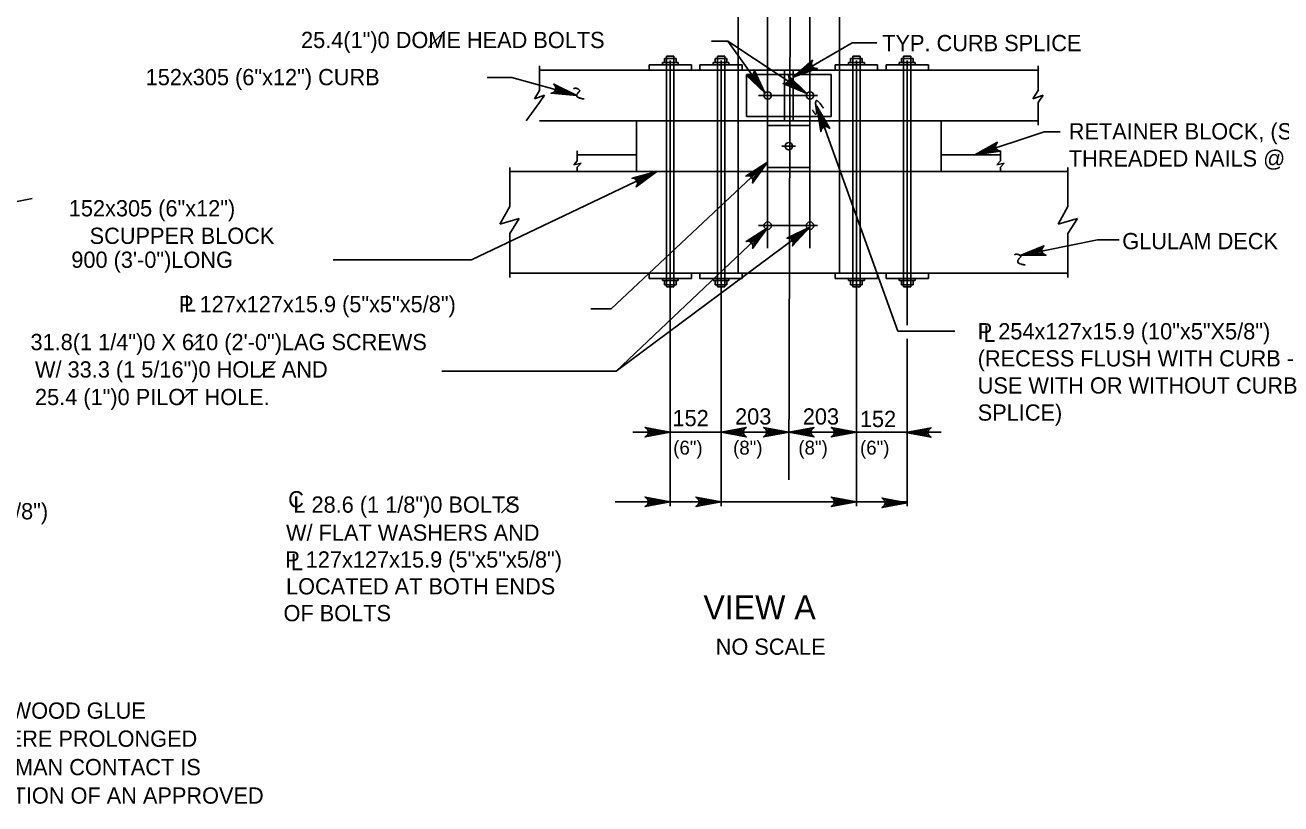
# Model space of a CAD drawing. Extents: x 0 to 36.3, y -66 to 0.
# Drawn here: x 11.08 to 20.36, y -9.1 to -3.35 of the extents above; entities that cross this region are included whole.
import ezdxf

# ---------------------------------------------------------------- set-up
doc = ezdxf.new("R2010")
doc.units = 0
doc.layers.add('2', color=7, linetype='Continuous')
doc.layers.add('3', color=7, linetype='Continuous')

msp = doc.modelspace()

# ---------------------------------------------------------------- linework, layer by layer
at = {"layer": '2'}
for p, q in [((16.3484, -3.2731), (16.3484, -3.6793)), ((17.0984, -3.2731), (17.0984, -3.6793)), ((15.8052, -3.5934), (15.8912, -3.5934)), ((15.8052, -3.5934), (15.8052, -3.6247)), ((15.8209, -3.5778), (15.8756, -3.5778)), ((15.8209, -3.5778), (15.8209, -5.2809)), ((15.8756, -3.5778), (15.8756, -5.2809)), ((15.8912, -3.5934), (15.8912, -3.6247)), ((16.1803, -3.5934), (16.1803, -3.6247)), ((16.1803, -3.5934), (16.2662, -3.5934)), ((16.1959, -3.5778), (16.2506, -3.5778)), ((16.1959, -3.5778), (16.1959, -5.2809)), ((16.2506, -3.5778), (16.2506, -5.2809)), ((16.2662, -3.5934), (16.2662, -3.6247)), ((17.1803, -3.5934), (17.1803, -3.6247)), ((17.1803, -3.5934), (17.2662, -3.5934)), ((17.1959, -3.5778), (17.2506, -3.5778)), ((17.1959, -3.5778), (17.1959, -5.2809)), ((17.2506, -3.5778), (17.2506, -5.2809)), ((17.2662, -3.5934), (17.2662, -3.6247)), ((17.5553, -3.5934), (17.5553, -3.6247)), ((17.5553, -3.5934), (17.6412, -3.5934)), ((17.5709, -3.5778), (17.6256, -3.5778)), ((17.5709, -3.5778), (17.5709, -5.2809)), ((17.6256, -3.5778), (17.6256, -5.2809)), ((17.6412, -3.5934), (17.6412, -3.6247)), ((14.8827, -3.6481), (14.8827, -3.8301)), ((14.8827, -3.6793), (18.5641, -3.6793)), ((15.692, -3.6403), (15.692, -3.6793)), ((16.0045, -3.6403), (15.692, -3.6403)), ((15.7897, -3.6247), (15.9068, -3.6247)), ((15.7897, -3.6247), (15.7897, -3.6403)), ((15.9068, -3.6247), (15.9068, -3.6403)), ((16.0045, -3.6403), (16.0045, -3.6793)), ((16.067, -3.6403), (16.067, -3.6793)), ((16.3795, -3.6403), (16.067, -3.6403)), ((16.1647, -3.6247), (16.2818, -3.6247)), ((16.1647, -3.6247), (16.1647, -3.6403)), ((16.2818, -3.6247), (16.2818, -3.6403)), ((16.3484, -3.6793), (16.3484, -5.1793)), ((16.3795, -3.6403), (16.3795, -3.6793)), ((16.6922, -3.6793), (16.6922, -4.0543)), ((16.7547, -3.6793), (16.7547, -4.0543)), ((17.067, -3.6403), (17.067, -3.6793)), ((17.3795, -3.6403), (17.067, -3.6403)), ((17.0984, -3.6793), (17.0984, -5.1793)), ((17.1647, -3.6247), (17.2818, -3.6247)), ((17.1647, -3.6247), (17.1647, -3.6403)), ((17.2818, -3.6247), (17.2818, -3.6403)), ((17.3795, -3.6403), (17.3795, -3.6793)), ((17.7545, -3.6403), (17.442, -3.6403)), ((17.442, -3.6403), (17.442, -3.6793)), ((17.5397, -3.6247), (17.6568, -3.6247)), ((17.5397, -3.6247), (17.5397, -3.6403)), ((17.6568, -3.6247), (17.6568, -3.6403)), ((17.7545, -3.6403), (17.7545, -3.6793)), ((18.5641, -3.6481), (18.5641, -3.8301)), ((16.4109, -3.713), (17.0359, -3.713)), ((16.4109, -3.713), (16.4109, -4.0231)), ((17.0359, -3.713), (17.0359, -4.0231)), ((14.8827, -3.8301), (14.8454, -3.892)), ((14.8454, -3.892), (14.9197, -3.8642)), ((14.9197, -3.8642), (14.8827, -3.9198)), ((18.5641, -3.8301), (18.5268, -3.892)), ((18.5268, -3.892), (18.6011, -3.8642)), ((18.6011, -3.8642), (18.5641, -3.9198)), ((14.8827, -3.9198), (14.7831, -4.0545)), ((18.5641, -3.9198), (18.5641, -4.0856)), ((14.8827, -4.0543), (18.5641, -4.0543)), ((15.5984, -4.0543), (15.5984, -4.4293)), ((16.4109, -4.0231), (17.0359, -4.0231)), ((17.8484, -4.0543), (17.8484, -4.4293)), ((16.5672, -4.088), (16.5672, -4.3981)), ((16.5672, -4.088), (16.8797, -4.088)), ((16.8797, -4.088), (16.8797, -4.3981)), ((16.673, -4.2418), (16.7722, -4.2418)), ((15.1609, -4.3502), (15.1351, -4.3781)), ((15.1609, -4.2763), (15.1609, -4.3502)), ((15.1609, -4.3043), (15.5984, -4.3043)), ((17.8484, -4.3043), (18.2859, -4.3043)), ((18.2859, -4.3502), (18.2601, -4.3781)), ((18.2859, -4.2763), (18.2859, -4.3502)), ((14.6625, -4.3981), (14.6625, -4.6877)), ((14.6625, -4.4293), (18.7843, -4.4293)), ((15.1351, -4.3781), (15.1898, -4.3667)), ((15.1898, -4.3667), (15.1609, -4.3966)), ((15.1609, -4.3966), (15.1609, -4.4293)), ((16.5672, -4.3981), (16.8797, -4.3981)), ((18.2601, -4.3781), (18.3147, -4.3667)), ((18.3147, -4.3667), (18.2859, -4.3966)), ((18.2859, -4.3966), (18.2859, -4.4293)), ((18.7843, -4.3981), (18.7843, -4.6877)), ((14.6625, -4.6877), (14.5902, -4.8166)), ((18.7843, -4.6877), (18.7119, -4.8166)), ((14.5902, -4.8166), (14.7327, -4.7757)), ((14.7327, -4.7757), (14.6625, -4.8864)), ((18.7119, -4.8166), (18.8545, -4.7757)), ((18.8545, -4.7757), (18.7843, -4.8864)), ((14.6625, -4.8864), (14.6625, -5.2106)), ((18.7843, -4.8864), (18.7843, -5.2106)), ((14.6625, -5.1793), (18.7843, -5.1793)), ((15.692, -5.2184), (15.692, -5.1793)), ((16.0045, -5.2184), (16.0045, -5.1793)), ((16.067, -5.2184), (16.067, -5.1793)), ((16.3795, -5.2184), (16.3795, -5.1793)), ((17.067, -5.2184), (17.067, -5.1793)), ((17.3795, -5.2184), (17.3795, -5.1793)), ((17.442, -5.2184), (17.442, -5.1793)), ((17.7545, -5.2184), (17.7545, -5.1793)), ((16.0045, -5.2184), (15.692, -5.2184)), ((15.7897, -5.2341), (15.7897, -5.2184)), ((15.7897, -5.2341), (15.9068, -5.2341)), ((15.8052, -5.2653), (15.8052, -5.2341)), ((15.8052, -5.2653), (15.8912, -5.2653)), ((15.8209, -5.2809), (15.8756, -5.2809)), ((15.8912, -5.2653), (15.8912, -5.2341)), ((15.9068, -5.2341), (15.9068, -5.2184)), ((16.3795, -5.2184), (16.067, -5.2184)), ((16.1647, -5.2341), (16.1647, -5.2184)), ((16.1647, -5.2341), (16.2818, -5.2341)), ((16.1803, -5.2653), (16.1803, -5.2341)), ((16.1803, -5.2653), (16.2662, -5.2653)), ((16.1959, -5.2809), (16.2506, -5.2809)), ((16.2662, -5.2653), (16.2662, -5.2341)), ((16.2818, -5.2341), (16.2818, -5.2184)), ((17.3795, -5.2184), (17.067, -5.2184)), ((17.1647, -5.2341), (17.1647, -5.2184)), ((17.1647, -5.2341), (17.2818, -5.2341)), ((17.1803, -5.2653), (17.1803, -5.2341)), ((17.1803, -5.2653), (17.2662, -5.2653)), ((17.1959, -5.2809), (17.2506, -5.2809)), ((17.2662, -5.2653), (17.2662, -5.2341)), ((17.2818, -5.2341), (17.2818, -5.2184)), ((17.7545, -5.2184), (17.442, -5.2184)), ((17.5397, -5.2341), (17.5397, -5.2184)), ((17.5397, -5.2341), (17.6568, -5.2341)), ((17.5553, -5.2653), (17.5553, -5.2341)), ((17.5553, -5.2653), (17.6412, -5.2653)), ((17.5709, -5.2809), (17.6256, -5.2809)), ((17.6412, -5.2653), (17.6412, -5.2341)), ((17.6568, -5.2341), (17.6568, -5.2184))]:
    msp.add_line(p, q, dxfattribs=at)
for centre in [(16.5672, -3.8669), (16.8797, -3.8669), (16.7234, -4.2419), (16.5672, -4.8286), (16.8797, -4.8286)]:
    msp.add_circle(centre, 0.0273, dxfattribs=at)
at = {"layer": '3'}
for p, q in [((16.7368, -1.4887), (16.7234, -6.7043)), ((16.5672, -2.1467), (16.5672, -4.994)), ((16.8797, -2.1467), (16.8797, -4.994)), ((14.0634, -3.5122), (14.1826, -3.393)), ((16.2725, -3.467), (16.1525, -3.467)), ((16.5472, -3.8483), (16.2725, -3.467)), ((16.8565, -3.8523), (16.2725, -3.467)), ((16.7547, -3.7311), (17.1906, -3.4787)), ((17.1906, -3.4787), (17.3745, -3.4787)), ((15.8484, -3.6095), (15.8484, -6.8987)), ((16.2234, -3.6095), (16.2234, -6.8987)), ((17.2234, -3.6095), (17.2234, -6.8987)), ((17.5984, -3.6095), (17.5984, -5.5642)), ((14.6769, -3.7332), (14.4954, -3.7332)), ((15.1572, -3.8669), (14.6769, -3.7332)), ((16.4994, -3.8668), (16.9362, -3.8668)), ((16.9306, -3.9465), (17.5277, -5.6086)), ((18.0983, -4.3043), (18.6085, -4.1353)), ((18.6085, -4.1353), (18.7285, -4.1353)), ((15.7489, -4.4293), (14.381, -5.0798)), ((16.5672, -4.3607), (15.411, -5.4423)), ((10.5034, -4.7528), (11.1361, -4.6288)), ((16.8797, -4.8385), (15.4482, -5.9023)), ((16.5672, -4.8436), (15.4482, -5.9023)), ((16.4994, -4.8285), (16.9362, -4.8285)), ((18.4324, -5.0499), (19.0042, -4.9333)), ((19.0042, -4.9333), (19.1629, -4.9333)), ((14.381, -5.0799), (13.3579, -5.0799)), ((15.411, -5.4423), (15.2622, -5.4423)), ((12.2935, -5.7468), (12.4016, -5.6387)), ((17.5277, -5.6086), (17.9496, -5.6086)), ((17.5984, -5.6651), (17.5984, -6.8987)), ((12.8198, -5.9429), (12.9324, -5.8303)), ((15.4482, -5.9023), (14.161, -5.9023)), ((12.2218, -6.1395), (12.3231, -6.0383)), ((15.5712, -6.3537), (17.8485, -6.3537)), ((14.6014, -6.9501), (14.7197, -6.8318)), ((15.4414, -6.8675), (17.5984, -6.8675))]:
    msp.add_line(p, q, dxfattribs=at)
for points in [[(16.7547, -3.7311), (16.8985, -3.6074), (16.8911, -3.6233), (16.8909, -3.6378), (16.8953, -3.6497), (16.9034, -3.6594), (16.9161, -3.6665), (16.9335, -3.6679), (16.7547, -3.7311), (16.9161, -3.6665), (16.9034, -3.6594), (16.7547, -3.7311), (16.8953, -3.6497), (16.8909, -3.6378), (16.7547, -3.7311), (16.8911, -3.6233)], [(16.5472, -3.8483), (16.4098, -3.7175), (16.4263, -3.7233), (16.4408, -3.7221), (16.4522, -3.7165), (16.4611, -3.7074), (16.4669, -3.6941), (16.4666, -3.6767), (16.5472, -3.8483), (16.4669, -3.6941), (16.4611, -3.7074), (16.5472, -3.8483), (16.4522, -3.7165), (16.4408, -3.7221), (16.5472, -3.8483), (16.4263, -3.7233)], [(15.1572, -3.8669), (14.9683, -3.8506), (14.9848, -3.8448), (14.9952, -3.8348), (15.0007, -3.8233), (15.002, -3.8108), (14.9982, -3.7967), (14.9871, -3.7832), (15.1572, -3.8669), (14.9982, -3.7967), (15.002, -3.8108), (15.1572, -3.8669), (15.0007, -3.8233), (14.9952, -3.8348), (15.1572, -3.8669), (14.9848, -3.8448)], [(16.8565, -3.8523), (16.6817, -3.7788), (16.6991, -3.7784), (16.7122, -3.7721), (16.7208, -3.7628), (16.726, -3.7512), (16.7267, -3.7367), (16.7202, -3.7205), (16.8565, -3.8523), (16.7267, -3.7367), (16.726, -3.7512), (16.8565, -3.8523), (16.7208, -3.7628), (16.7122, -3.7721), (16.8565, -3.8523), (16.6991, -3.7784)], [(16.9306, -3.9465), (17.0265, -4.1101), (17.0122, -4.1), (16.998, -4.0972), (16.9855, -4.0994), (16.9745, -4.1057), (16.9653, -4.1168), (16.9608, -4.1338), (16.9306, -3.9465), (16.9653, -4.1168), (16.9745, -4.1057), (16.9306, -3.9465), (16.9855, -4.0994), (16.998, -4.0972), (16.9306, -3.9465), (17.0122, -4.1)], [(18.0983, -4.3043), (18.2643, -4.2125), (18.2538, -4.2265), (18.2507, -4.2407), (18.2526, -4.2532), (18.2586, -4.2644), (18.2695, -4.2739), (18.2862, -4.2788), (18.0983, -4.3043), (18.2695, -4.2739), (18.2586, -4.2644), (18.0983, -4.3043), (18.2526, -4.2532), (18.2507, -4.2407), (18.0983, -4.3043), (18.2538, -4.2265)], [(15.7489, -4.4293), (15.5956, -4.5409), (15.6042, -4.5258), (15.6056, -4.5113), (15.6022, -4.4991), (15.5948, -4.4887), (15.5828, -4.4807), (15.5656, -4.4778), (15.7489, -4.4293), (15.5828, -4.4807), (15.5948, -4.4887), (15.7489, -4.4293), (15.6022, -4.4991), (15.6056, -4.5113), (15.7489, -4.4293), (15.6042, -4.5258)], [(16.5672, -4.3607), (16.4549, -4.5137), (16.4586, -4.4966), (16.4555, -4.4823), (16.4485, -4.4718), (16.4384, -4.4641), (16.4244, -4.46), (16.4072, -4.4626), (16.5672, -4.3607), (16.4244, -4.46), (16.4384, -4.4641), (16.5672, -4.3607), (16.4485, -4.4718), (16.4555, -4.4823), (16.5672, -4.3607), (16.4586, -4.4966)], [(16.5672, -4.8436), (16.4557, -4.9971), (16.4594, -4.98), (16.4562, -4.9658), (16.4492, -4.9552), (16.439, -4.9477), (16.425, -4.9437), (16.4078, -4.9463), (16.5672, -4.8436), (16.425, -4.9437), (16.439, -4.9477), (16.5672, -4.8436), (16.4492, -4.9552), (16.4562, -4.9658), (16.5672, -4.8436), (16.4594, -4.98)], [(16.8797, -4.8385), (16.7509, -4.9777), (16.7565, -4.9612), (16.755, -4.9467), (16.7492, -4.9354), (16.7401, -4.9267), (16.7267, -4.9211), (16.7092, -4.9217), (16.8797, -4.8385), (16.7267, -4.9211), (16.7401, -4.9267), (16.8797, -4.8385), (16.7492, -4.9354), (16.755, -4.9467), (16.8797, -4.8385), (16.7565, -4.9612)], [(18.4324, -5.0499), (18.6081, -4.9784), (18.596, -4.991), (18.5912, -5.0047), (18.5917, -5.0174), (18.5962, -5.0293), (18.606, -5.04), (18.6221, -5.0469), (18.4324, -5.0499), (18.606, -5.04), (18.5962, -5.0293), (18.4324, -5.0499), (18.5917, -5.0174), (18.5912, -5.0047), (18.4324, -5.0499), (18.596, -4.991)], [(15.8484, -6.3537), (15.662, -6.3886), (15.6763, -6.3787), (15.6837, -6.3662), (15.6859, -6.3537), (15.6837, -6.3412), (15.6763, -6.3287), (15.662, -6.3187), (15.8484, -6.3537), (15.6763, -6.3287), (15.6837, -6.3412), (15.8484, -6.3537), (15.6859, -6.3537), (15.6837, -6.3662), (15.8484, -6.3537), (15.6763, -6.3787)], [(16.2234, -6.3537), (16.4098, -6.3187), (16.3955, -6.3287), (16.3881, -6.3412), (16.3859, -6.3537), (16.3881, -6.3662), (16.3955, -6.3787), (16.4098, -6.3886), (16.2234, -6.3537), (16.3955, -6.3787), (16.3881, -6.3662), (16.2234, -6.3537), (16.3859, -6.3537), (16.3881, -6.3412), (16.2234, -6.3537), (16.3955, -6.3287)], [(16.7234, -6.3537), (16.537, -6.3886), (16.5513, -6.3787), (16.5587, -6.3662), (16.5609, -6.3537), (16.5587, -6.3412), (16.5513, -6.3287), (16.537, -6.3187), (16.7234, -6.3537), (16.5513, -6.3287), (16.5587, -6.3412), (16.7234, -6.3537), (16.5609, -6.3537), (16.5587, -6.3662), (16.7234, -6.3537), (16.5513, -6.3787)], [(16.7234, -6.3537), (16.9098, -6.3886), (16.8955, -6.3787), (16.8881, -6.3662), (16.8859, -6.3537), (16.8881, -6.3412), (16.8955, -6.3287), (16.9098, -6.3187), (16.7234, -6.3537), (16.8955, -6.3287), (16.8881, -6.3412), (16.7234, -6.3537), (16.8859, -6.3537), (16.8881, -6.3662), (16.7234, -6.3537), (16.8955, -6.3787)], [(17.2234, -6.3537), (17.037, -6.3886), (17.0513, -6.3787), (17.0587, -6.3662), (17.0609, -6.3537), (17.0587, -6.3412), (17.0513, -6.3287), (17.037, -6.3187), (17.2234, -6.3537), (17.0513, -6.3287), (17.0587, -6.3412), (17.2234, -6.3537), (17.0609, -6.3537), (17.0587, -6.3662), (17.2234, -6.3537), (17.0513, -6.3787)], [(17.5882, -6.3553), (17.7746, -6.3204), (17.7602, -6.3303), (17.7528, -6.3428), (17.7507, -6.3553), (17.7528, -6.3678), (17.7602, -6.3803), (17.7746, -6.3903), (17.5882, -6.3553), (17.7602, -6.3803), (17.7528, -6.3678), (17.5882, -6.3553), (17.7507, -6.3553), (17.7528, -6.3428), (17.5882, -6.3553), (17.7602, -6.3303)], [(15.8484, -6.8675), (15.662, -6.9024), (15.6763, -6.8925), (15.6837, -6.88), (15.6859, -6.8675), (15.6837, -6.855), (15.6763, -6.8425), (15.662, -6.8326), (15.8484, -6.8675), (15.6763, -6.8425), (15.6837, -6.855), (15.8484, -6.8675), (15.6859, -6.8675), (15.6837, -6.88), (15.8484, -6.8675), (15.6763, -6.8925)], [(16.2234, -6.8675), (16.037, -6.9024), (16.0513, -6.8925), (16.0587, -6.88), (16.0609, -6.8675), (16.0587, -6.855), (16.0513, -6.8425), (16.037, -6.8326), (16.2234, -6.8675), (16.0513, -6.8425), (16.0587, -6.855), (16.2234, -6.8675), (16.0609, -6.8675), (16.0587, -6.88), (16.2234, -6.8675), (16.0513, -6.8925)], [(17.2234, -6.8675), (17.037, -6.9024), (17.0513, -6.8925), (17.0587, -6.88), (17.0609, -6.8675), (17.0587, -6.855), (17.0513, -6.8425), (17.037, -6.8326), (17.2234, -6.8675), (17.0513, -6.8425), (17.0587, -6.855), (17.2234, -6.8675), (17.0609, -6.8675), (17.0587, -6.88), (17.2234, -6.8675), (17.0513, -6.8925)], [(17.5984, -6.8749), (17.412, -6.9098), (17.4263, -6.8999), (17.4337, -6.8874), (17.4359, -6.8749), (17.4337, -6.8624), (17.4263, -6.8499), (17.412, -6.8399), (17.5984, -6.8749), (17.4263, -6.8499), (17.4337, -6.8624), (17.5984, -6.8749), (17.4359, -6.8749), (17.4337, -6.8874), (17.5984, -6.8749), (17.4263, -6.8999)]]:
    msp.add_lwpolyline(points, dxfattribs=at)
for points in [[(16.8685, -3.6883), (16.8485, -3.6538), (16.7547, -3.7312)], [(16.4932, -3.7392), (16.4608, -3.7626), (16.5471, -3.8482)], [(16.7673, -3.7696), (16.7452, -3.8029), (16.8565, -3.8523)], [(18.2186, -4.2856), (18.206, -4.2476), (18.0983, -4.3043)], [(15.6318, -4.4628), (15.649, -4.499), (15.7487, -4.4293)], [(16.4603, -4.4322), (16.4887, -4.4627), (16.5658, -4.362)], [(16.4663, -4.9115), (16.4938, -4.9405), (16.5672, -4.8434)], [(16.7553, -4.9059), (16.7791, -4.9382), (16.8637, -4.8507)]]:
    msp.add_lwpolyline(points, close=True, dxfattribs=at)
for centre, radius, start, end in [((15.1519, -3.8527), 0.0394, 101.24, 119.22297), ((15.149, -3.8383), 0.0248, 78.5013, 101.24), ((15.1423, -3.8713), 0.0585, 68.55376, 78.5013), ((15.1749, -3.8648), 0.0178, 177.1104, 204.86978), ((15.168, -3.8645), 0.0109, 141.43841, 177.1104), ((15.1771, -3.8638), 0.0201, 204.86978, 233.05634), ((15.8701, -4.4241), 0.9087, 141.12339, 141.43841), ((18.1116, -6.2313), 3.788, 140.96911, 141.12339), ((15.1509, -3.8494), 0.0349, 55.672, 68.55376), ((15.1859, -3.8521), 0.0348, 233.05634, 254.40037), ((15.7889, -4.3484), 0.798, 140.21634, 140.9691), ((15.1501, -3.8506), 0.0364, 35.62317, 55.672), ((14.9692, -3.6658), 0.2687, 320.21634, 321.51358), ((15.2504, -3.6208), 0.2749, 254.40037, 256.19123), ((15.1772, -3.8312), 0.00303, 321.51357, 35.62317), ((15.2832, -3.4877), 0.412, 256.19123, 257.65415), ((15.2204, -3.7743), 0.1187, 257.65415, 260.92719), ((15.2426, -3.6356), 0.2591, 260.92719, 263.14214), ((18.4088, -5.0781), 0.0394, 101.24, 119.22297), ((18.406, -5.0637), 0.0248, 78.5013, 101.24), ((18.3993, -5.0967), 0.0585, 68.55376, 78.5013), ((18.425, -5.0899), 0.0109, 141.43841, 177.1104), ((18.4319, -5.0902), 0.0178, 177.1104, 204.86978), ((18.434, -5.0892), 0.0201, 204.86978, 233.05634), ((19.127, -5.6495), 0.9087, 141.12339, 141.43841), ((21.3685, -7.4567), 3.788, 140.96911, 141.12339), ((18.4079, -5.0748), 0.0349, 55.672, 68.55376), ((19.0459, -5.5738), 0.798, 140.21634, 140.9691), ((18.4071, -5.076), 0.0364, 35.62317, 55.672), ((18.2262, -4.8912), 0.2687, 320.21634, 321.51358), ((18.4341, -5.0566), 0.00303, 321.51357, 35.62317), ((18.4428, -5.0775), 0.0348, 233.05634, 254.40037), ((18.5074, -4.8462), 0.2749, 254.40037, 256.19123), ((18.5401, -4.7131), 0.412, 256.19123, 257.65415), ((18.4774, -4.9997), 0.1187, 257.65415, 260.92719), ((18.4996, -4.861), 0.2591, 260.92719, 263.14214)]:
    msp.add_arc(centre, radius, start, end, dxfattribs=at)
msp.add_open_spline([(16.8977, -3.972), (16.9383, -4.0492), (16.9097, -3.8536), (16.9789, -3.9615)], degree=2, dxfattribs=at)

# ---------------------------------------------------------------- texts
at = {"layer": '2'}
msp.add_text('VIEW A', height=0.17717, dxfattribs=at).set_placement((16.093, -7.7348))
at = {"layer": '3'}
for s, height, p in [('25.4(1")0 DOME HEAD BOLTS', 0.12, (13.1212, -3.5173)), ('TYP. CURB SPLICE', 0.12, (17.4137, -3.5401)), ('152x305 (6"x12") CURB', 0.12, (11.9737, -3.7915)), ('RETAINER BLOCK, (SECURE WITH 20d', 0.12, (18.7912, -4.1917)), ('THREADED NAILS @ 300 (12")O.C.)', 0.12, (18.7912, -4.392)), ('152x305 (6"x12")', 0.12, (11.4059, -4.7599)), ('SCUPPER BLOCK', 0.12, (11.5599, -4.9632)), ('GLULAM DECK', 0.12, (19.1861, -5.0023)), ('900 (3\'-0")LONG', 0.12, (11.4246, -5.14)), ('P 127x127x15.9 (5"x5"x5/8")', 0.12, (12.22, -5.4681)), ('L', 0.12, (12.2576, -5.4629)), ('P 254x127x15.9 (10"x5"X5/8")', 0.12, (18.1187, -5.6683)), ('31.8(1 1/4")0 X 610 (2\'-0")LAG SCREWS', 0.12, (11.1232, -5.7479)), ('L', 0.12, (18.1607, -5.6866)), ('(RECESS FLUSH WITH CURB -', 0.12, (18.1187, -5.8683)), ('W/ 33.3 (1 5/16")0 HOLE AND', 0.12, (11.1564, -5.9502)), ('25.4 (1")0 PILOT HOLE.', 0.12, (11.1564, -6.1536)), ('USE WITH OR WITHOUT CURB', 0.12, (18.1187, -6.0683)), ('152', 0.12, (15.8643, -6.3096)), ('203', 0.12, (16.3269, -6.2973)), ('203', 0.12, (16.8269, -6.2973)), ('152', 0.12, (17.2486, -6.3157)), ('SPLICE)', 0.12, (18.1187, -6.2683)), ('(6")', 0.10289, (15.87, -6.519)), ('(8")', 0.10292, (16.3122, -6.519)), ('(8")', 0.10292, (16.7942, -6.519)), ('(6")', 0.10289, (17.2497, -6.519)), ('C', 0.12, (13.0262, -6.9092)), ('L 28.6 (1 1/8")0 BOLTS', 0.12, (13.0646, -6.948)), ('AND P 127x127x15.9 (5"x5"x5/8")', 0.12, (8.8257, -6.9971)), ('W/ FLAT WASHERS AND', 0.12, (13.0103, -7.1552)), ('P 127x127x15.9 (5"x5"x5/8")', 0.12, (13.0041, -7.3534)), ('L', 0.12, (13.0457, -7.3733)), ('LOCATED AT BOTH ENDS', 0.12, (13.0103, -7.5515)), ('OF BOLTS', 0.12, (12.9916, -7.7497)), ('NO SCALE', 0.12, (16.1837, -7.9974)), ('2.) DO NOT USE TREATED HARDWOOD GLUE', 0.12, (8.4533, -8.4693)), ('LAMINATED RAILINGS WHERE PROLONGED', 0.12, (8.9308, -8.6765)), ('EXPOSURE TO DIRECT HUMAN CONTACT IS', 0.12, (8.9308, -8.8865)), ('LIKELY WITHOUT APPLICATION OF AN APPROVED', 0.12, (8.9308, -9.0964))]:
    msp.add_text(s, height=height, dxfattribs=at).set_placement(p)

doc.saveas('drawing.dxf')
